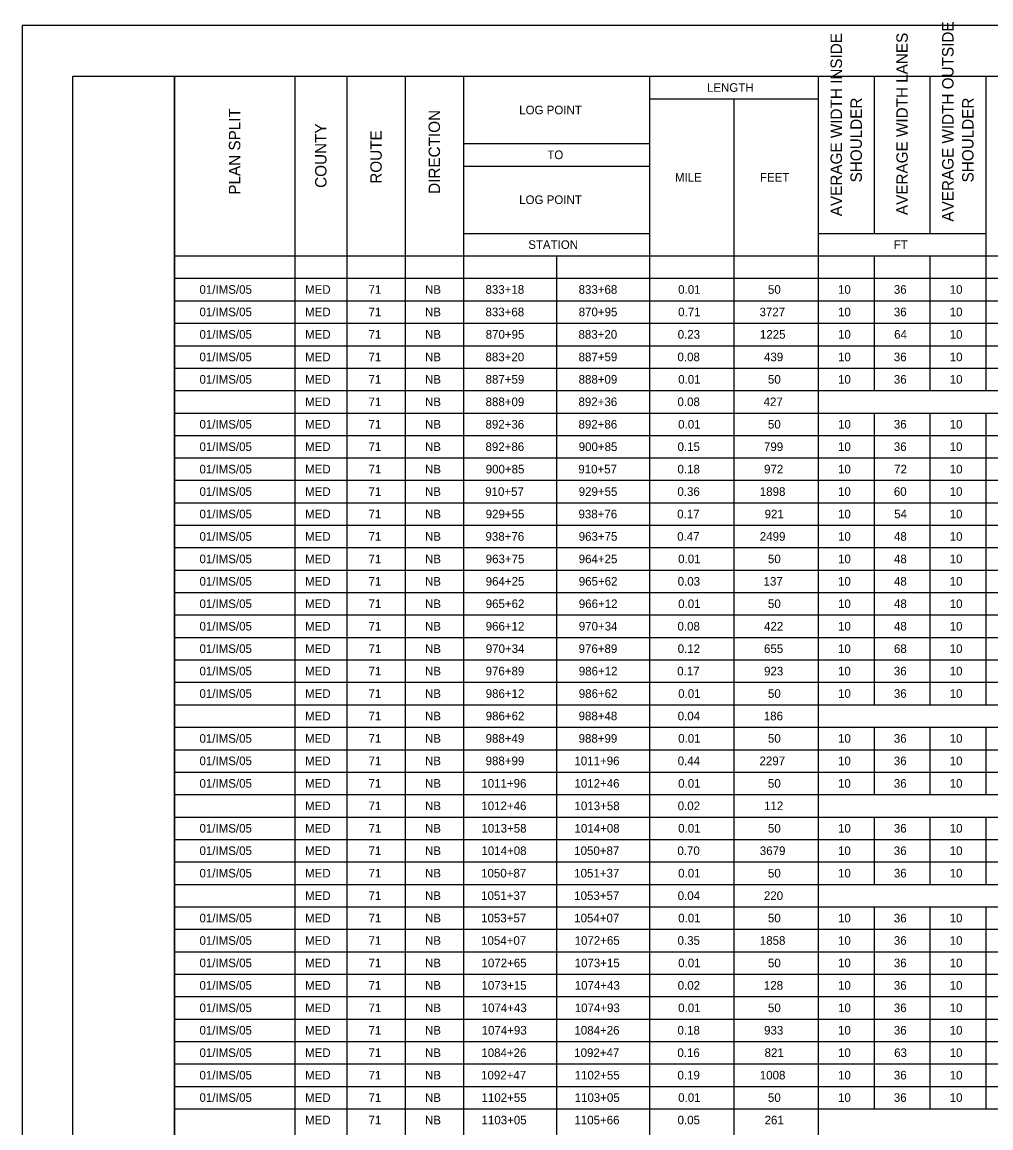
# Model space of a CAD drawing. Extents: x 0 to 34, y 0 to 22.3.
# Drawn here: x 0 to 9.54, y 11.14 to 22.03 of the extents above; entities that cross this region are included whole.
import ezdxf

# ---------------------------------------------------------------- set-up
doc = ezdxf.new("R2010")
doc.units = 0
for name, color, linetype in [('SH_Border', 7, 'Continuous'), ('SH_Cut_Line', 7, 'Continuous'), ('SH_Text', 7, 'Continuous')]:
    doc.layers.add(name, color=color, linetype=linetype)

msp = doc.modelspace()

# ---------------------------------------------------------------- linework, layer by layer
at = {"layer": 'SH_Border'}
for points in [[(0.5, 21.5), (1.5, 21.5), (1.5, 0.5), (0.5, 0.5)], [(1.5, 21.5), (33.5, 21.5), (33.5, 0.5), (1.5, 0.5)]]:
    msp.add_lwpolyline(points, close=True, dxfattribs=at)
at = {"layer": 'SH_Cut_Line'}
msp.add_lwpolyline([(0, 0), (34, 0), (34, 22), (0, 22)], close=True, dxfattribs=at)
at = {"layer": 'SH_Text'}
for p, q in [((1.5, 21.5), (32, 21.5)), ((1.5, 21.5), (1.5, 19.732)), ((2.685, 21.5), (2.685, 4.037)), ((3.199, 21.5), (3.199, 4.037)), ((3.773, 21.5), (3.773, 4.037)), ((4.347, 21.5), (4.347, 4.037)), ((6.18, 21.5), (6.18, 0.721)), ((7.842, 21.5), (7.842, 0.5)), ((8.392, 21.5), (8.392, 19.953)), ((8.942, 21.5), (8.942, 19.953)), ((9.492, 21.5), (9.492, 18.405)), ((6.18, 21.279), (7.842, 21.279)), ((7.011, 21.279), (7.011, 0.721)), ((4.347, 20.837), (6.18, 20.837)), ((4.347, 20.616), (6.18, 20.616)), ((4.347, 19.953), (6.18, 19.953)), ((7.842, 19.953), (9.492, 19.953)), ((1.5, 19.732), (32, 19.732)), ((1.5, 19.732), (1.5, 0.5)), ((5.264, 19.732), (5.264, 4.037)), ((8.392, 19.732), (8.392, 18.405)), ((8.942, 19.732), (8.942, 18.405)), ((1.5, 19.511), (32, 19.511)), ((1.5, 19.289), (32, 19.289)), ((1.5, 19.068), (32, 19.068)), ((1.5, 18.847), (32, 18.847)), ((1.5, 18.626), (32, 18.626)), ((1.5, 18.405), (32, 18.405)), ((1.5, 18.184), (32, 18.184)), ((8.392, 18.184), (8.392, 15.311)), ((8.942, 18.184), (8.942, 15.311)), ((9.492, 18.184), (9.492, 15.311)), ((1.5, 17.963), (32, 17.963)), ((1.5, 17.742), (32, 17.742)), ((1.5, 17.521), (32, 17.521)), ((1.5, 17.3), (32, 17.3)), ((1.5, 17.079), (32, 17.079)), ((1.5, 16.858), (32, 16.858)), ((1.5, 16.637), (32, 16.637)), ((1.5, 16.416), (32, 16.416)), ((1.5, 16.195), (32, 16.195)), ((1.5, 15.974), (32, 15.974)), ((1.5, 15.753), (32, 15.753)), ((1.5, 15.532), (32, 15.532)), ((1.5, 15.311), (32, 15.311)), ((1.5, 15.089), (32, 15.089)), ((8.392, 15.089), (8.392, 14.426)), ((8.942, 15.089), (8.942, 14.426)), ((9.492, 15.089), (9.492, 14.426)), ((1.5, 14.868), (32, 14.868)), ((1.5, 14.647), (32, 14.647)), ((1.5, 14.426), (32, 14.426)), ((1.5, 14.205), (32, 14.205)), ((8.392, 14.205), (8.392, 13.542)), ((8.942, 14.205), (8.942, 13.542)), ((9.492, 14.205), (9.492, 13.542)), ((1.5, 13.984), (32, 13.984)), ((1.5, 13.763), (32, 13.763)), ((1.5, 13.542), (32, 13.542)), ((1.5, 13.321), (32, 13.321)), ((8.392, 13.321), (8.392, 11.332)), ((8.942, 13.321), (8.942, 11.332)), ((9.492, 13.321), (9.492, 11.332)), ((1.5, 13.1), (32, 13.1)), ((1.5, 12.879), (32, 12.879)), ((1.5, 12.658), (32, 12.658)), ((1.5, 12.437), (32, 12.437)), ((1.5, 12.216), (32, 12.216)), ((1.5, 11.995), (32, 11.995)), ((1.5, 11.774), (32, 11.774)), ((1.5, 11.553), (32, 11.553)), ((1.5, 11.332), (32, 11.332))]:
    msp.add_line(p, q, dxfattribs=at)

# ---------------------------------------------------------------- texts
for s, height, p in [('AVERAGE WIDTH OUTSIDE ', 0.11242, (9.174, 20.069)), ('AVERAGE WIDTH INSIDE ', 0.11242, (8.075, 20.122)), ('AVERAGE WIDTH LANES', 0.11242, (8.723, 20.133)), ('SHOULDER', 0.1124, (8.271, 20.455)), ('SHOULDER', 0.1124, (9.371, 20.455)), ('PLAN SPLIT', 0.1124, (2.149, 20.334)), ('DIRECTION', 0.1124, (4.116, 20.342)), ('COUNTY', 0.1124, (2.998, 20.401)), ('ROUTE', 0.1124, (3.542, 20.442))]:
    msp.add_text(s, height=height, rotation=90, dxfattribs=at).set_placement(p)
for s, p in [('LENGTH', (6.745, 21.347)), ('LOG POINT', (4.896, 21.126)), ('TO', (5.173, 20.684)), ('MILE', (6.43, 20.463)), ('FEET', (7.267, 20.463)), ('LOG POINT', (4.896, 20.242)), ('STATION', (4.985, 19.8)), ('FT', (8.585, 19.8)), ('01/IMS/05', (1.747, 19.358)), ('MED', (2.787, 19.358)), ('71', (3.412, 19.358)), ('NB', (3.968, 19.358)), ('833+18', (4.564, 19.358)), ('833+68', (5.481, 19.358)), ('0.01', (6.462, 19.358)), ('50', (7.346, 19.358)), ('10', (8.036, 19.358)), ('36', (8.586, 19.358)), ('10', (9.136, 19.358)), ('01/IMS/05', (1.747, 19.137)), ('MED', (2.787, 19.137)), ('71', (3.412, 19.137)), ('NB', (3.968, 19.137)), ('833+68', (4.564, 19.137)), ('870+95', (5.482, 19.137)), ('0.71', (6.462, 19.137)), ('3727', (7.263, 19.137)), ('10', (8.036, 19.137)), ('36', (8.586, 19.137)), ('10', (9.136, 19.137)), ('01/IMS/05', (1.747, 18.916)), ('MED', (2.787, 18.916)), ('71', (3.412, 18.916)), ('NB', (3.968, 18.916)), ('870+95', (4.566, 18.916)), ('883+20', (5.48, 18.916)), ('0.23', (6.457, 18.916)), ('1225', (7.267, 18.916)), ('10', (8.036, 18.916)), ('64', (8.589, 18.916)), ('10', (9.136, 18.916)), ('01/IMS/05', (1.747, 18.694)), ('MED', (2.787, 18.694)), ('71', (3.412, 18.694)), ('NB', (3.968, 18.694)), ('883+20', (4.564, 18.694)), ('887+59', (5.481, 18.694)), ('0.08', (6.455, 18.694)), ('439', (7.307, 18.694)), ('10', (8.036, 18.694)), ('36', (8.586, 18.694)), ('10', (9.136, 18.694)), ('01/IMS/05', (1.747, 18.473)), ('MED', (2.787, 18.473)), ('71', (3.412, 18.473)), ('NB', (3.968, 18.473)), ('887+59', (4.565, 18.473)), ('888+09', (5.481, 18.473)), ('0.01', (6.462, 18.473)), ('50', (7.346, 18.473)), ('10', (8.036, 18.473)), ('36', (8.586, 18.473)), ('10', (9.136, 18.473)), ('MED', (2.787, 18.252)), ('71', (3.412, 18.252)), ('NB', (3.968, 18.252)), ('888+09', (4.565, 18.252)), ('892+36', (5.48, 18.252)), ('0.08', (6.455, 18.252)), ('427', (7.303, 18.252)), ('01/IMS/05', (1.747, 18.031)), ('MED', (2.787, 18.031)), ('71', (3.412, 18.031)), ('NB', (3.968, 18.031)), ('892+36', (4.564, 18.031)), ('892+86', (5.48, 18.031)), ('0.01', (6.462, 18.031)), ('50', (7.346, 18.031)), ('10', (8.036, 18.031)), ('36', (8.586, 18.031)), ('10', (9.136, 18.031)), ('01/IMS/05', (1.747, 17.81)), ('MED', (2.787, 17.81)), ('71', (3.412, 17.81)), ('NB', (3.968, 17.81)), ('892+86', (4.564, 17.81)), ('900+85', (5.482, 17.81)), ('0.15', (6.456, 17.81)), ('799', (7.307, 17.81)), ('10', (8.036, 17.81)), ('36', (8.586, 17.81)), ('10', (9.136, 17.81)), ('01/IMS/05', (1.747, 17.589)), ('MED', (2.787, 17.589)), ('71', (3.412, 17.589)), ('NB', (3.968, 17.589)), ('900+85', (4.566, 17.589)), ('910+57', (5.478, 17.589)), ('0.18', (6.455, 17.589)), ('972', (7.308, 17.589)), ('10', (8.036, 17.589)), ('72', (8.589, 17.589)), ('10', (9.136, 17.589)), ('01/IMS/05', (1.747, 17.368)), ('MED', (2.787, 17.368)), ('71', (3.412, 17.368)), ('NB', (3.968, 17.368)), ('910+57', (4.561, 17.368)), ('929+55', (5.482, 17.368)), ('0.36', (6.454, 17.368)), ('1898', (7.266, 17.368)), ('10', (8.036, 17.368)), ('60', (8.586, 17.368)), ('10', (9.136, 17.368)), ('01/IMS/05', (1.747, 17.147)), ('MED', (2.787, 17.147)), ('71', (3.412, 17.147)), ('NB', (3.968, 17.147)), ('929+55', (4.566, 17.147)), ('938+76', (5.48, 17.147)), ('0.17', (6.452, 17.147)), ('921', (7.313, 17.147)), ('10', (8.036, 17.147)), ('54', (8.589, 17.147)), ('10', (9.136, 17.147)), ('01/IMS/05', (1.747, 16.926)), ('MED', (2.787, 16.926)), ('71', (3.412, 16.926)), ('NB', (3.968, 16.926)), ('938+76', (4.564, 16.926)), ('963+75', (5.482, 16.926)), ('0.47', (6.452, 16.926)), ('2499', (7.266, 16.926)), ('10', (8.036, 16.926)), ('48', (8.587, 16.926)), ('10', (9.136, 16.926)), ('01/IMS/05', (1.747, 16.705)), ('MED', (2.787, 16.705)), ('71', (3.412, 16.705)), ('NB', (3.968, 16.705)), ('963+75', (4.566, 16.705)), ('964+25', (5.482, 16.705)), ('0.01', (6.462, 16.705)), ('50', (7.346, 16.705)), ('10', (8.036, 16.705)), ('48', (8.587, 16.705)), ('10', (9.136, 16.705)), ('01/IMS/05', (1.747, 16.484)), ('MED', (2.787, 16.484)), ('71', (3.412, 16.484)), ('NB', (3.968, 16.484)), ('964+25', (4.566, 16.484)), ('965+62', (5.483, 16.484)), ('0.03', (6.457, 16.484)), ('137', (7.303, 16.484)), ('10', (8.036, 16.484)), ('48', (8.587, 16.484)), ('10', (9.136, 16.484)), ('01/IMS/05', (1.747, 16.263)), ('MED', (2.787, 16.263)), ('71', (3.412, 16.263)), ('NB', (3.968, 16.263)), ('965+62', (4.566, 16.263)), ('966+12', (5.483, 16.263)), ('0.01', (6.462, 16.263)), ('50', (7.346, 16.263)), ('10', (8.036, 16.263)), ('48', (8.587, 16.263)), ('10', (9.136, 16.263)), ('01/IMS/05', (1.747, 16.042)), ('MED', (2.787, 16.042)), ('71', (3.412, 16.042)), ('NB', (3.968, 16.042)), ('966+12', (4.566, 16.042)), ('970+34', (5.483, 16.042)), ('0.08', (6.455, 16.042)), ('422', (7.308, 16.042)), ('10', (8.036, 16.042)), ('48', (8.587, 16.042)), ('10', (9.136, 16.042)), ('01/IMS/05', (1.747, 15.821)), ('MED', (2.787, 15.821)), ('71', (3.412, 15.821)), ('NB', (3.968, 15.821)), ('970+34', (4.567, 15.821)), ('976+89', (5.481, 15.821)), ('0.12', (6.457, 15.821)), ('655', (7.307, 15.821)), ('10', (8.036, 15.821)), ('68', (8.587, 15.821)), ('10', (9.136, 15.821)), ('01/IMS/05', (1.747, 15.6)), ('MED', (2.787, 15.6)), ('71', (3.412, 15.6)), ('NB', (3.968, 15.6)), ('976+89', (4.565, 15.6)), ('986+12', (5.483, 15.6)), ('0.17', (6.452, 15.6)), ('923', (7.308, 15.6)), ('10', (8.036, 15.6)), ('36', (8.586, 15.6)), ('10', (9.136, 15.6)), ('01/IMS/05', (1.747, 15.379)), ('MED', (2.787, 15.379)), ('71', (3.412, 15.379)), ('NB', (3.968, 15.379)), ('986+12', (4.566, 15.379)), ('986+62', (5.483, 15.379)), ('0.01', (6.462, 15.379)), ('50', (7.346, 15.379)), ('10', (8.036, 15.379)), ('36', (8.586, 15.379)), ('10', (9.136, 15.379)), ('MED', (2.787, 15.158)), ('71', (3.412, 15.158)), ('NB', (3.968, 15.158)), ('986+62', (4.566, 15.158)), ('988+48', (5.481, 15.158)), ('0.04', (6.457, 15.158)), ('186', (7.305, 15.158)), ('01/IMS/05', (1.747, 14.937)), ('MED', (2.787, 14.937)), ('71', (3.412, 14.937)), ('NB', (3.968, 14.937)), ('988+49', (4.565, 14.937)), ('988+99', (5.481, 14.937)), ('0.01', (6.462, 14.937)), ('50', (7.346, 14.937)), ('10', (8.036, 14.937)), ('36', (8.586, 14.937)), ('10', (9.136, 14.937)), ('01/IMS/05', (1.747, 14.716)), ('MED', (2.787, 14.716)), ('71', (3.412, 14.716)), ('NB', (3.968, 14.716)), ('988+99', (4.565, 14.716)), ('1011+96', (5.44, 14.716)), ('0.44', (6.457, 14.716)), ('2297', (7.263, 14.716)), ('10', (8.036, 14.716)), ('36', (8.586, 14.716)), ('10', (9.136, 14.716)), ('01/IMS/05', (1.747, 14.494)), ('MED', (2.787, 14.494)), ('71', (3.412, 14.494)), ('NB', (3.968, 14.494)), ('1011+96', (4.523, 14.494)), ('1012+46', (5.44, 14.494)), ('0.01', (6.462, 14.494)), ('50', (7.346, 14.494)), ('10', (8.036, 14.494)), ('36', (8.586, 14.494)), ('10', (9.136, 14.494)), ('MED', (2.787, 14.273)), ('71', (3.412, 14.273)), ('NB', (3.968, 14.273)), ('1012+46', (4.523, 14.273)), ('1013+58', (5.441, 14.273)), ('0.02', (6.457, 14.273)), ('112', (7.308, 14.273)), ('01/IMS/05', (1.747, 14.052)), ('MED', (2.787, 14.052)), ('71', (3.412, 14.052)), ('NB', (3.968, 14.052)), ('1013+58', (4.524, 14.052)), ('1014+08', (5.441, 14.052)), ('0.01', (6.462, 14.052)), ('50', (7.346, 14.052)), ('10', (8.036, 14.052)), ('36', (8.586, 14.052)), ('10', (9.136, 14.052)), ('01/IMS/05', (1.747, 13.831)), ('MED', (2.787, 13.831)), ('71', (3.412, 13.831)), ('NB', (3.968, 13.831)), ('1014+08', (4.524, 13.831)), ('1050+87', (5.438, 13.831)), ('0.70', (6.454, 13.831)), ('3679', (7.266, 13.831)), ('10', (8.036, 13.831)), ('36', (8.586, 13.831)), ('10', (9.136, 13.831)), ('01/IMS/05', (1.747, 13.61)), ('MED', (2.787, 13.61)), ('71', (3.412, 13.61)), ('NB', (3.968, 13.61)), ('1050+87', (4.521, 13.61)), ('1051+37', (5.438, 13.61)), ('0.01', (6.462, 13.61)), ('50', (7.346, 13.61)), ('10', (8.036, 13.61)), ('36', (8.586, 13.61)), ('10', (9.136, 13.61)), ('MED', (2.787, 13.389)), ('71', (3.412, 13.389)), ('NB', (3.968, 13.389)), ('1051+37', (4.521, 13.389)), ('1053+57', (5.438, 13.389)), ('0.04', (6.457, 13.389)), ('220', (7.306, 13.389)), ('01/IMS/05', (1.747, 13.168)), ('MED', (2.787, 13.168)), ('71', (3.412, 13.168)), ('NB', (3.968, 13.168)), ('1053+57', (4.521, 13.168)), ('1054+07', (5.438, 13.168)), ('0.01', (6.462, 13.168)), ('50', (7.346, 13.168)), ('10', (8.036, 13.168)), ('36', (8.586, 13.168)), ('10', (9.136, 13.168)), ('01/IMS/05', (1.747, 12.947)), ('MED', (2.787, 12.947)), ('71', (3.412, 12.947)), ('NB', (3.968, 12.947)), ('1054+07', (4.521, 12.947)), ('1072+65', (5.442, 12.947)), ('0.35', (6.456, 12.947)), ('1858', (7.266, 12.947)), ('10', (8.036, 12.947)), ('36', (8.586, 12.947)), ('10', (9.136, 12.947)), ('01/IMS/05', (1.747, 12.726)), ('MED', (2.787, 12.726)), ('71', (3.412, 12.726)), ('NB', (3.968, 12.726)), ('1072+65', (4.525, 12.726)), ('1073+15', (5.442, 12.726)), ('0.01', (6.462, 12.726)), ('50', (7.346, 12.726)), ('10', (8.036, 12.726)), ('36', (8.586, 12.726)), ('10', (9.136, 12.726)), ('01/IMS/05', (1.747, 12.505)), ('MED', (2.787, 12.505)), ('71', (3.412, 12.505)), ('NB', (3.968, 12.505)), ('1073+15', (4.525, 12.505)), ('1074+43', (5.443, 12.505)), ('0.02', (6.457, 12.505)), ('128', (7.306, 12.505)), ('10', (8.036, 12.505)), ('36', (8.586, 12.505)), ('10', (9.136, 12.505)), ('01/IMS/05', (1.747, 12.284)), ('MED', (2.787, 12.284)), ('71', (3.412, 12.284)), ('NB', (3.968, 12.284)), ('1074+43', (4.526, 12.284)), ('1074+93', (5.443, 12.284)), ('0.01', (6.462, 12.284)), ('50', (7.346, 12.284)), ('10', (8.036, 12.284)), ('36', (8.586, 12.284)), ('10', (9.136, 12.284)), ('01/IMS/05', (1.747, 12.063)), ('MED', (2.787, 12.063)), ('71', (3.412, 12.063)), ('NB', (3.968, 12.063)), ('1074+93', (4.526, 12.063)), ('1084+26', (5.44, 12.063)), ('0.18', (6.455, 12.063)), ('933', (7.308, 12.063)), ('10', (8.036, 12.063)), ('36', (8.586, 12.063)), ('10', (9.136, 12.063)), ('01/IMS/05', (1.747, 11.842)), ('MED', (2.787, 11.842)), ('71', (3.412, 11.842)), ('NB', (3.968, 11.842)), ('1084+26', (4.523, 11.842)), ('1092+47', (5.438, 11.842)), ('0.16', (6.454, 11.842)), ('821', (7.313, 11.842)), ('10', (8.036, 11.842)), ('63', (8.589, 11.842)), ('10', (9.136, 11.842)), ('01/IMS/05', (1.747, 11.621)), ('MED', (2.787, 11.621)), ('71', (3.412, 11.621)), ('NB', (3.968, 11.621)), ('1092+47', (4.521, 11.621)), ('1102+55', (5.442, 11.621)), ('0.19', (6.455, 11.621)), ('1008', (7.266, 11.621)), ('10', (8.036, 11.621)), ('36', (8.586, 11.621)), ('10', (9.136, 11.621)), ('01/IMS/05', (1.747, 11.4)), ('MED', (2.787, 11.4)), ('71', (3.412, 11.4)), ('NB', (3.968, 11.4)), ('1102+55', (4.525, 11.4)), ('1103+05', (5.442, 11.4)), ('0.01', (6.462, 11.4)), ('50', (7.346, 11.4)), ('10', (8.036, 11.4)), ('36', (8.586, 11.4)), ('10', (9.136, 11.4)), ('MED', (2.787, 11.179)), ('71', (3.412, 11.179)), ('NB', (3.968, 11.179)), ('1103+05', (4.525, 11.179)), ('1105+66', (5.44, 11.179)), ('0.05', (6.456, 11.179)), ('261', (7.313, 11.179))]:
    msp.add_text(s, height=0.0847, dxfattribs=at).set_placement(p)

doc.saveas('drawing.dxf')
